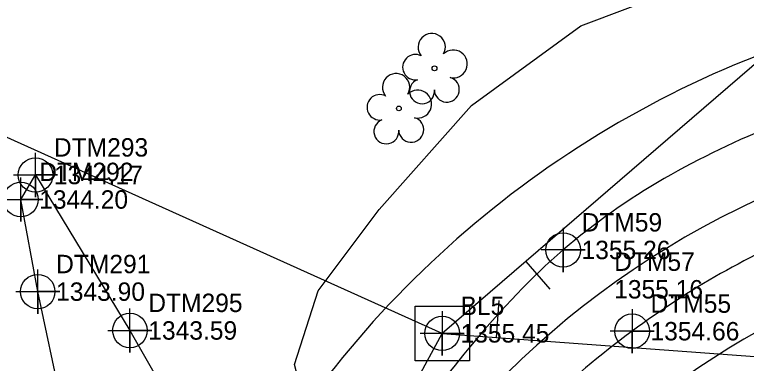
# Model space of a CAD drawing. Extents: x 1435573 to 1437263, y 981340 to 982884.
# Drawn here: x 1436162.6 to 1436262.2, y 982438.5 to 982485.9 of the extents above; entities that cross this region are included whole.
import ezdxf

# ---------------------------------------------------------------- set-up
doc = ezdxf.new("R2010")
doc.units = 0
for name, color, linetype in [('CTL Supplemental Horizontal and Vertical CELL', 7, 'Continuous'), ('Default Symbol CELL', 7, 'Continuous'), ('Default Symbol Cogo Elevation', 7, 'Continuous'), ('Default Symbol Cogo Number', 7, 'Continuous'), ('Exist DTM Crownline Cogo Elevation', 7, 'Continuous'), ('Exist DTM Crownline Cogo Number', 7, 'Continuous'), ('Exist Horizontal Alignment', 7, 'Continuous'), ('Exist Horizontal Baseline Alignment', 7, 'Continuous'), ('Exist Horizontal Baseline Alignment Station Label', 7, 'Continuous'), ('Exist Horizontal Baseline Alignment Tick small', 7, 'Continuous'), ('Exist Hydro Stream or Body of Water', 7, 'Continuous'), ('Exist Hydro Stream or Body of Water Cogo Elevation', 7, 'Continuous'), ('Exist Hydro Stream or Body of Water Cogo Number', 7, 'Continuous'), ('Exist Hydro Stream or Body of Water Cogo Point CELL', 7, 'Continuous'), ('Exist Other Culture Fence Line', 7, 'Continuous'), ('Exist Right of Way Line', 7, 'Continuous'), ('Exist Roads EOP', 7, 'Continuous'), ('Exist Roads EOP Cogo Elevation', 7, 'Continuous'), ('Exist Roads EOP Cogo Number', 7, 'Continuous'), ('Exist Roads EOP Cogo Point CELL', 7, 'Continuous'), ('Exist Vegetation Tree CELL', 7, 'Continuous')]:
    doc.layers.add(name, color=color, linetype=linetype)

# ---------------------------------------------------------------- blocks, each defined once
blk = doc.blocks.new('CTL SUPPLEMENTAL HORIZONTAL AND VERTICAL')
at = {"layer": 'CTL Supplemental Horizontal and Vertical CELL'}
blk.add_line((0, 0), (0, 0), dxfattribs=at)
blk.add_lwpolyline([(-0.0735, 0.074), (0.07475, 0.074), (0.07475, -0.0745), (-0.0735, -0.0745)], close=True, dxfattribs=at)

msp = doc.modelspace()

# ---------------------------------------------------------------- linework, layer by layer
at = {"layer": 'Default Symbol CELL'}
msp.add_lwpolyline([(1436220.786, 982445.589), (1436220.786, 982439.589), (1436220.786, 982442.589), (1436223.786, 982442.589), (1436217.786, 982442.589)], dxfattribs=at)
msp.add_circle((1436220.786, 982442.589), 2.344, dxfattribs=at)
at = {"layer": 'Exist Horizontal Alignment'}
msp.add_arc((1436313.923, 982351.784), 120, 105.381, 148.00538, dxfattribs=at)
at = {"layer": 'Exist Horizontal Baseline Alignment'}
for p, q in [((1436383.798, 982582.769), (1436220.786, 982442.589)), ((1435840.714, 981747.053), (1436220.786, 982442.589)), ((1436220.786, 982442.589), (1436692.101, 982407.772))]:
    msp.add_line(p, q, dxfattribs=at)
at = {"layer": 'Exist Horizontal Baseline Alignment Station Label'}
msp.add_line((1436220.786, 982442.589), (1435992.647, 982545.095), dxfattribs=at)
at = {"layer": 'Exist Horizontal Baseline Alignment Tick small'}
for p, q in [((1436232.156, 982452.367), (1436235.416, 982448.576)), ((1436228.16, 982442.045), (1436228.528, 982447.031))]:
    msp.add_line(p, q, dxfattribs=at)
at = {"layer": 'Exist Hydro Stream or Body of Water'}
msp.add_lwpolyline([(1436183.197, 982401.145), (1436174.856, 982420.702), (1436169.03, 982433.135), (1436165.791, 982448.257), (1436163.489, 982460.767), (1436165.486, 982464.097), (1436178.322, 982442.984), (1436188.107, 982425.852), (1436193.959, 982409.317), (1436185.234, 982400.934)], dxfattribs=at)
at = {"layer": 'Exist Hydro Stream or Body of Water Cogo Point CELL'}
for points in [[(1436162.486, 982464.097), (1436168.486, 982464.097), (1436165.486, 982464.097), (1436165.486, 982461.097), (1436165.486, 982467.097)], [(1436160.489, 982460.767), (1436166.489, 982460.767), (1436163.489, 982460.767), (1436163.489, 982457.767), (1436163.489, 982463.767)], [(1436162.791, 982448.257), (1436168.791, 982448.257), (1436165.791, 982448.257), (1436165.791, 982445.257), (1436165.791, 982451.257)], [(1436175.322, 982442.984), (1436181.322, 982442.984), (1436178.322, 982442.984), (1436178.322, 982439.984), (1436178.322, 982445.984)]]:
    msp.add_lwpolyline(points, dxfattribs=at)
for centre in [(1436165.486, 982464.097), (1436163.489, 982460.767), (1436165.791, 982448.257), (1436178.322, 982442.984)]:
    msp.add_circle(centre, 2.344, dxfattribs=at)
at = {"layer": 'Exist Other Culture Fence Line'}
msp.add_lwpolyline([(1436202.59, 982431.055), (1436200.709, 982438.366), (1436203.906, 982448.344), (1436212.22, 982459.418), (1436224.761, 982473.514), (1436239.649, 982484.365), (1436252.414, 982489.179), (1436268.307, 982493.586), (1436286.755, 982496.538), (1436305.357, 982497.936), (1436327.325, 982497.136), (1436350.276, 982494.304), (1436373.208, 982490.334), (1436397.213, 982484.177), (1436408.323, 982480.682)], dxfattribs=at)
at = {"layer": 'Exist Right of Way Line'}
for radius in [138, 104]:
    msp.add_arc((1436313.923, 982351.784), radius, 105.381, 148.00538, dxfattribs=at)
at = {"layer": 'Exist Roads EOP'}
for points in [[(1436588.992, 982441.11), (1436549.29, 982447.24), (1436506.499, 982454.101), (1436466.305, 982461.645), (1436427.312, 982468.116), (1436386.362, 982474.42), (1436348, 982479.527), (1436317.909, 982480.777), (1436294.782, 982478.72), (1436266.251, 982470.951), (1436237.241, 982453.917), (1436214.303, 982427.574)], [(1436586.861, 982425.386), (1436547.068, 982432.003), (1436503.748, 982439.002), (1436464.176, 982445.58), (1436424.483, 982452.266), (1436384.263, 982458.258), (1436345.936, 982463.434), (1436318.115, 982465.285), (1436296.639, 982463.742), (1436271.588, 982456.954), (1436246.618, 982442.883), (1436222.427, 982421.486)]]:
    msp.add_spline(points, degree=3, dxfattribs=at)
at = {"layer": 'Exist Roads EOP Cogo Point CELL'}
for points in [[(1436237.241, 982456.917), (1436237.241, 982450.917), (1436237.241, 982453.917), (1436240.241, 982453.917), (1436234.241, 982453.917)], [(1436246.618, 982445.883), (1436246.618, 982439.883), (1436246.618, 982442.883), (1436249.618, 982442.883), (1436243.618, 982442.883)]]:
    msp.add_lwpolyline(points, dxfattribs=at)
for centre in [(1436237.241, 982453.917), (1436246.618, 982442.883)]:
    msp.add_circle(centre, 2.344, dxfattribs=at)
at = {"layer": 'Exist Vegetation Tree CELL'}
for p, q in [((1436219.747, 982478.583), (1436219.747, 982478.583)), ((1436214.9, 982473.135), (1436214.9, 982473.135))]:
    msp.add_line(p, q, dxfattribs=at)
for centre in [(1436219.747, 982478.583), (1436214.9, 982473.135)]:
    msp.add_circle(centre, 0.326, dxfattribs=at)
for centre, radius, start, end in [((1436219.362, 982481.456), 1.856, 330.16508, 219.71335), ((1436222.296, 982479.172), 1.899, 257.1011, 134.19993), ((1436217.142, 982478.737), 1.727, 62.66361, 279.3457), ((1436214.515, 982476.008), 1.856, 330.16508, 219.71335), ((1436221.42, 982475.683), 1.698, 181.28216, 74.55999), ((1436218.043, 982475.462), 1.689, 111.56708, 6.23104), ((1436217.449, 982473.723), 1.899, 257.1011, 134.19993), ((1436212.295, 982473.289), 1.727, 62.66361, 279.3457), ((1436213.196, 982470.014), 1.689, 111.56708, 6.23104), ((1436216.573, 982470.235), 1.698, 181.28216, 74.55999)]:
    msp.add_arc(centre, radius, start, end, dxfattribs=at)

# ---------------------------------------------------------------- block references
at = {"layer": 'CTL Supplemental Horizontal and Vertical CELL', "xscale": 50, "yscale": 50}
msp.add_blockref('CTL SUPPLEMENTAL HORIZONTAL AND VERTICAL', (1436220.786, 982442.589), dxfattribs=at)

# ---------------------------------------------------------------- texts
at = {"layer": 'Default Symbol Cogo Elevation'}
msp.add_text('1355.45', height=2.5, dxfattribs=at).set_placement((1436223.286, 982441.339))
at = {"layer": 'Default Symbol Cogo Number'}
msp.add_text('BL5', height=2.5, dxfattribs=at).set_placement((1436223.286, 982445.089))
at = {"layer": 'Exist DTM Crownline Cogo Elevation'}
msp.add_text('1355.16', height=2.5, dxfattribs=at).set_placement((1436244.176, 982447.327))
at = {"layer": 'Exist DTM Crownline Cogo Number'}
msp.add_text('DTM57', height=2.5, dxfattribs=at).set_placement((1436244.176, 982451.077))
at = {"layer": 'Exist Hydro Stream or Body of Water Cogo Elevation'}
for s, p in [('1344.17', (1436167.986, 982462.847)), ('1344.20', (1436165.989, 982459.517)), ('1343.90', (1436168.291, 982447.008)), ('1343.59', (1436180.822, 982441.734))]:
    msp.add_text(s, height=2.5, dxfattribs=at).set_placement(p)
at = {"layer": 'Exist Hydro Stream or Body of Water Cogo Number'}
for s, p in [('DTM293', (1436167.986, 982466.597)), ('DTM292', (1436165.989, 982463.267)), ('DTM291', (1436168.291, 982450.758)), ('DTM295', (1436180.822, 982445.484))]:
    msp.add_text(s, height=2.5, dxfattribs=at).set_placement(p)
at = {"layer": 'Exist Roads EOP Cogo Elevation'}
for s, p in [('1355.26', (1436239.741, 982452.667)), ('1354.66', (1436249.118, 982441.633))]:
    msp.add_text(s, height=2.5, dxfattribs=at).set_placement(p)
at = {"layer": 'Exist Roads EOP Cogo Number'}
for s, p in [('DTM59', (1436239.741, 982456.417)), ('DTM55', (1436249.118, 982445.383))]:
    msp.add_text(s, height=2.5, dxfattribs=at).set_placement(p)

doc.saveas('drawing.dxf')
